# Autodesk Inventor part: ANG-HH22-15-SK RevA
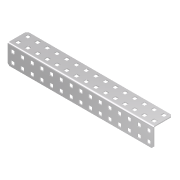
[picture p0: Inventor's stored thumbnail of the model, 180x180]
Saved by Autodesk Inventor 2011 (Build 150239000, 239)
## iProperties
Created: 2007-12
Part Number: ANG-HH22-15-SK RevA
Document SubType Name: Modeling
Density: 1 g/cm^3
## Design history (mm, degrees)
feature "Base1"
workplane "Work Plane1"
workplane "Work Plane2"
sketch "Sketch1" dims "d5" = 25.4
  geometry: L1 (2.286, -23.419)-(188.214, -23.419) reference; L2 (188.214, -23.419)-(190.5, -21.133) reference; L3 (190.5, -21.133)-(190.5, 0) reference; L4 (0, 0)-(190.5, 0) reference; L5 (0, 0)-(0, -21.133) reference; L6 (0, -21.133)-(2.286, -23.419) reference; L7 (186.461, -3.734)-(186.461, -7.341) reference; L8 (185.953, -7.849)-(182.347, -7.849) reference; L9 (181.839, -7.341)-(181.839, -3.734) reference; L10 (182.347, -3.226)-(185.953, -3.226) reference; L11 (173.761, -16.434)-(173.761, -20.041) reference; L12 (173.253, -20.549)-(169.647, -20.549) reference; L13 (169.139, -20.041)-(169.139, -16.434) reference; L14 (169.647, -15.926)-(173.253, -15.926) reference; L15 (173.761, -3.734)-(173.761, -7.341) reference; L16 (173.253, -7.849)-(169.647, -7.849) reference; L17 (169.139, -7.341)-(169.139, -3.734) reference; L18 (169.647, -3.226)-(173.253, -3.226) reference; L19 (161.061, -16.434)-(161.061, -20.041) reference; L20 (160.553, -20.549)-(156.947, -20.549) reference; L21 (156.439, -20.041)-(156.439, -16.434) reference; L22 (156.947, -15.926)-(160.553, -15.926) reference; L23 (161.061, -3.734)-(161.061, -7.341) reference; L24 (160.553, -7.849)-(156.947, -7.849) reference; L25 (156.439, -7.341)-(156.439, -3.734) reference; L26 (156.947, -3.226)-(160.553, -3.226) reference; L27 (148.361, -16.434)-(148.361, -20.041) reference; L28 (147.853, -20.549)-(144.247, -20.549) reference; L29 (143.739, -20.041)-(143.739, -16.434) reference; L30 (144.247, -15.926)-(147.853, -15.926) reference; L31 (148.361, -3.734)-(148.361, -7.341) reference; L32 (147.853, -7.849)-(144.247, -7.849) reference; L33 (143.739, -7.341)-(143.739, -3.734) reference; L34 (144.247, -3.226)-(147.853, -3.226) reference; L35 (135.661, -16.434)-(135.661, -20.041) reference; L36 (135.153, -20.549)-(131.547, -20.549) reference; L37 (131.039, -20.041)-(131.039, -16.434) reference; L38 (131.547, -15.926)-(135.153, -15.926) reference; L39 (135.661, -3.734)-(135.661, -7.341) reference; L40 (135.153, -7.849)-(131.547, -7.849) reference; L41 (131.039, -7.341)-(131.039, -3.734) reference; L42 (131.547, -3.226)-(135.153, -3.226) reference; L43 (122.961, -16.434)-(122.961, -20.041) reference; L44 (122.453, -20.549)-(118.847, -20.549) reference; L45 (118.339, -20.041)-(118.339, -16.434) reference; L46 (118.847, -15.926)-(122.453, -15.926) reference; L47 (122.961, -3.734)-(122.961, -7.341) reference; L48 (122.453, -7.849)-(118.847, -7.849) reference; L49 (118.339, -7.341)-(118.339, -3.734) reference; L50 (118.847, -3.226)-(122.453, -3.226) reference; L51 (110.261, -16.434)-(110.261, -20.041) reference; L52 (109.753, -20.549)-(106.147, -20.549) reference; L53 (105.639, -20.041)-(105.639, -16.434) reference; L54 (106.147, -15.926)-(109.753, -15.926) reference; L55 (110.261, -3.734)-(110.261, -7.341) reference; L56 (109.753, -7.849)-(106.147, -7.849) reference; L57 (105.639, -7.341)-(105.639, -3.734) reference; L58 (106.147, -3.226)-(109.753, -3.226) reference; L59 (97.561, -16.434)-(97.561, -20.041) reference; L60 (97.053, -20.549)-(93.447, -20.549) reference; L61 (92.939, -20.041)-(92.939, -16.434) reference; L62 (93.447, -15.926)-(97.053, -15.926) reference; L63 (97.561, -3.734)-(97.561, -7.341) reference; L64 (97.053, -7.849)-(93.447, -7.849) reference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; C1 r 2.311 at (184.15, -18.237); C2 r 2.311 at (171.45, -18.237); C3 r 2.311 at (158.75, -18.237); C4 r 2.311 at (146.05, -18.237); C5 r 2.311 at (133.35, -18.237); C6 r 2.311 at (120.65, -18.237); C7 r 2.311 at (107.95, -18.237); C8 r 2.311 at (95.25, -18.237); C9 r 2.311 at (82.55, -18.237); C10 r 2.311 at (69.85, -18.237); C11 r 2.311 at (57.15, -18.237); C12 r 2.311 at (44.45, -18.237); C13 r 2.311 at (31.75, -18.237); C14 r 2.311 at (19.05, -18.237); C15 r 2.311 at (6.35, -18.237); A1 r 0.508 centre (185.953, -7.341) between (185.953, -7.849) and (186.461, -7.341) reference; A2 r 0.508 centre (182.347, -7.341) between (181.839, -7.341) and (182.347, -7.849) reference; A3 r 0.508 centre (182.347, -3.734) between (182.347, -3.226) and (181.839, -3.734) reference; A4 r 0.508 centre (185.953, -3.734) between (186.461, -3.734) and (185.953, -3.226) reference; A5 r 0.508 centre (173.253, -20.041) between (173.253, -20.549) and (173.761, -20.041) reference; A6 r 0.508 centre (169.647, -20.041) between (169.139, -20.041) and (169.647, -20.549) reference; A7 r 0.508 centre (169.647, -16.434) between (169.647, -15.926) and (169.139, -16.434) reference; A8 r 0.508 centre (173.253, -16.434) between (173.761, -16.434) and (173.253, -15.926) reference; A9 r 0.508 centre (173.253, -7.341) between (173.253, -7.849) and (173.761, -7.341) reference; A10 r 0.508 centre (169.647, -7.341) between (169.139, -7.341) and (169.647, -7.849) reference; A11 r 0.508 centre (169.647, -3.734) between (169.647, -3.226) and (169.139, -3.734) reference; A12 r 0.508 centre (173.253, -3.734) between (173.761, -3.734) and (173.253, -3.226) reference; A13 r 0.508 centre (160.553, -20.041) between (160.553, -20.549) and (161.061, -20.041) reference; A14 r 0.508 centre (156.947, -20.041) between (156.439, -20.041) and (156.947, -20.549) reference; A15 r 0.508 centre (156.947, -16.434) between (156.947, -15.926) and (156.439, -16.434) reference; A16 r 0.508 centre (160.553, -16.434) between (161.061, -16.434) and (160.553, -15.926) reference; A17 r 0.508 centre (160.553, -7.341) between (160.553, -7.849) and (161.061, -7.341) reference; A18 r 0.508 centre (156.947, -7.341) between (156.439, -7.341) and (156.947, -7.849) reference; A19 r 0.508 centre (156.947, -3.734) between (156.947, -3.226) and (156.439, -3.734) reference; A20 r 0.508 centre (160.553, -3.734) between (161.061, -3.734) and (160.553, -3.226) reference; A21 r 0.508 centre (147.853, -20.041) between (147.853, -20.549) and (148.361, -20.041) reference; A22 r 0.508 centre (144.247, -20.041) between (143.739, -20.041) and (144.247, -20.549) reference; A23 r 0.508 centre (144.247, -16.434) between (144.247, -15.926) and (143.739, -16.434) reference; A24 r 0.508 centre (147.853, -16.434) between (148.361, -16.434) and (147.853, -15.926) reference; A25 r 0.508 centre (147.853, -7.341) between (147.853, -7.849) and (148.361, -7.341) reference; A26 r 0.508 centre (144.247, -7.341) between (143.739, -7.341) and (144.247, -7.849) reference; A27 r 0.508 centre (144.247, -3.734) between (144.247, -3.226) and (143.739, -3.734) reference; A28 r 0.508 centre (147.853, -3.734) between (148.361, -3.734) and (147.853, -3.226) reference; A29 r 0.508 centre (135.153, -20.041) between (135.153, -20.549) and (135.661, -20.041) reference; A30 r 0.508 centre (131.547, -20.041) between (131.039, -20.041) and (131.547, -20.549) reference; A31 r 0.508 centre (131.547, -16.434) between (131.547, -15.926) and (131.039, -16.434) reference; A32 r 0.508 centre (135.153, -16.434) between (135.661, -16.434) and (135.153, -15.926) reference; A33 r 0.508 centre (135.153, -7.341) between (135.153, -7.849) and (135.661, -7.341) reference; A34 r 0.508 centre (131.547, -7.341) between (131.039, -7.341) and (131.547, -7.849) reference; A35 r 0.508 centre (131.547, -3.734) between (131.547, -3.226) and (131.039, -3.734) reference; A36 r 0.508 centre (135.153, -3.734) between (135.661, -3.734) and (135.153, -3.226) reference; A37 r 0.508 centre (122.453, -20.041) between (122.453, -20.549) and (122.961, -20.041) reference; A38 r 0.508 centre (118.847, -20.041) between (118.339, -20.041) and (118.847, -20.549) reference; A39 r 0.508 centre (118.847, -16.434) between (118.847, -15.926) and (118.339, -16.434) reference; A40 r 0.508 centre (122.453, -16.434) between (122.961, -16.434) and (122.453, -15.926) reference; A41 r 0.508 centre (122.453, -7.341) between (122.453, -7.849) and (122.961, -7.341) reference; A42 r 0.508 centre (118.847, -7.341) between (118.339, -7.341) and (118.847, -7.849) reference; A43 r 0.508 centre (118.847, -3.734) between (118.847, -3.226) and (118.339, -3.734) reference; A44 r 0.508 centre (122.453, -3.734) between (122.961, -3.734) and (122.453, -3.226) reference; A45 r 0.508 centre (109.753, -20.041) between (109.753, -20.549) and (110.261, -20.041) reference; A46 r 0.508 centre (106.147, -20.041) between (105.639, -20.041) and (106.147, -20.549) reference; A47 r 0.508 centre (106.147, -16.434) between (106.147, -15.926) and (105.639, -16.434) reference; A48 r 0.508 centre (109.753, -16.434) between (110.261, -16.434) and (109.753, -15.926) reference; A49 r 0.508 centre (109.753, -7.341) between (109.753, -7.849) and (110.261, -7.341) reference; A50 r 0.508 centre (106.147, -7.341) between (105.639, -7.341) and (106.147, -7.849) reference; A51 r 0.508 centre (106.147, -3.734) between (106.147, -3.226) and (105.639, -3.734) reference; A52 r 0.508 centre (109.753, -3.734) between (110.261, -3.734) and (109.753, -3.226) reference; A53 r 0.508 centre (97.053, -20.041) between (97.053, -20.549) and (97.561, -20.041) reference; A54 r 0.508 centre (93.447, -20.041) between (92.939, -20.041) and (93.447, -20.549) reference; A55 r 0.508 centre (93.447, -16.434) between (93.447, -15.926) and (92.939, -16.434) reference; A56 r 0.508 centre (97.053, -16.434) between (97.561, -16.434) and (97.053, -15.926) reference; A57 r 0.508 centre (97.053, -7.341) between (97.053, -7.849) and (97.561, -7.341) reference; A58 r 0.508 centre (93.447, -7.341) between (92.939, -7.341) and (93.447, -7.849) reference; A59 r 0.508 centre (93.447, -3.734) between (93.447, -3.226) and (92.939, -3.734) reference; A60 r 0.508 centre (97.053, -3.734) between (97.561, -3.734) and (97.053, -3.226) reference; A61 r 0.508 centre (84.353, -20.041) between (84.353, -20.549) and (84.861, -20.041) reference; A62 r 0.508 centre (80.747, -20.041) between (80.239, -20.041) and (80.747, -20.549) reference; A63 r 0.508 centre (80.747, -16.434) between (80.747, -15.926) and (80.239, -16.434) reference; A64 r 0.508 centre (84.353, -16.434) between (84.861, -16.434) and (84.353, -15.926) reference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
  constraints: 15 centre point, 3 tangent, 1 horizontal, 28 other
  dimensions: "d2" = 12.7 distance of C1.centre C2.centre
sketch "Sketch2" dims "d12" = 25.4
  geometry: L1 (190.5, 21.133)-(190.5, 0) reference; L2 (190.5, 21.133)-(188.214, 23.419) reference; L3 (2.286, 23.419)-(188.214, 23.419) reference; L4 (2.286, 23.419)-(0, 21.133) reference; L5 (0, 0)-(0, 21.133) reference; L6 (190.5, 0)-(0, 0) reference; L7 (186.461, 7.341)-(186.461, 3.734) reference; L8 (185.953, 3.226)-(182.347, 3.226) reference; L9 (181.839, 3.734)-(181.839, 7.341) reference; L10 (182.347, 7.849)-(185.953, 7.849) reference; L11 (173.761, 20.041)-(173.761, 16.434) reference; L12 (173.253, 15.926)-(169.647, 15.926) reference; L13 (169.139, 16.434)-(169.139, 20.041) reference; L14 (169.647, 20.549)-(173.253, 20.549) reference; L15 (173.761, 7.341)-(173.761, 3.734) reference; L16 (173.253, 3.226)-(169.647, 3.226) reference; L17 (169.139, 3.734)-(169.139, 7.341) reference; L18 (169.647, 7.849)-(173.253, 7.849) reference; L19 (161.061, 20.041)-(161.061, 16.434) reference; L20 (160.553, 15.926)-(156.947, 15.926) reference; L21 (156.439, 16.434)-(156.439, 20.041) reference; L22 (156.947, 20.549)-(160.553, 20.549) reference; L23 (161.061, 7.341)-(161.061, 3.734) reference; L24 (160.553, 3.226)-(156.947, 3.226) reference; L25 (156.439, 3.734)-(156.439, 7.341) reference; L26 (156.947, 7.849)-(160.553, 7.849) reference; L27 (148.361, 20.041)-(148.361, 16.434) reference; L28 (147.853, 15.926)-(144.247, 15.926) reference; L29 (143.739, 16.434)-(143.739, 20.041) reference; L30 (144.247, 20.549)-(147.853, 20.549) reference; L31 (148.361, 7.341)-(148.361, 3.734) reference; L32 (147.853, 3.226)-(144.247, 3.226) reference; L33 (143.739, 3.734)-(143.739, 7.341) reference; L34 (144.247, 7.849)-(147.853, 7.849) reference; L35 (135.661, 20.041)-(135.661, 16.434) reference; L36 (135.153, 15.926)-(131.547, 15.926) reference; L37 (131.039, 16.434)-(131.039, 20.041) reference; L38 (131.547, 20.549)-(135.153, 20.549) reference; L39 (135.661, 7.341)-(135.661, 3.734) reference; L40 (135.153, 3.226)-(131.547, 3.226) reference; L41 (131.039, 3.734)-(131.039, 7.341) reference; L42 (131.547, 7.849)-(135.153, 7.849) reference; L43 (122.961, 20.041)-(122.961, 16.434) reference; L44 (122.453, 15.926)-(118.847, 15.926) reference; L45 (118.339, 16.434)-(118.339, 20.041) reference; L46 (118.847, 20.549)-(122.453, 20.549) reference; L47 (122.961, 7.341)-(122.961, 3.734) reference; L48 (122.453, 3.226)-(118.847, 3.226) reference; L49 (118.339, 3.734)-(118.339, 7.341) reference; L50 (118.847, 7.849)-(122.453, 7.849) reference; L51 (110.261, 20.041)-(110.261, 16.434) reference; L52 (109.753, 15.926)-(106.147, 15.926) reference; L53 (105.639, 16.434)-(105.639, 20.041) reference; L54 (106.147, 20.549)-(109.753, 20.549) reference; L55 (110.261, 7.341)-(110.261, 3.734) reference; L56 (109.753, 3.226)-(106.147, 3.226) reference; L57 (105.639, 3.734)-(105.639, 7.341) reference; L58 (106.147, 7.849)-(109.753, 7.849) reference; L59 (97.561, 20.041)-(97.561, 16.434) reference; L60 (97.053, 15.926)-(93.447, 15.926) reference; L61 (92.939, 16.434)-(92.939, 20.041) reference; L62 (93.447, 20.549)-(97.053, 20.549) reference; L63 (97.561, 7.341)-(97.561, 3.734) reference; L64 (97.053, 3.226)-(93.447, 3.226) reference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; C1 r 2.311 at (184.15, 18.237); C2 r 2.311 at (171.45, 18.237); C3 r 2.311 at (158.75, 18.237); C4 r 2.311 at (146.05, 18.237); C5 r 2.311 at (133.35, 18.237); C6 r 2.311 at (120.65, 18.237); C7 r 2.311 at (107.95, 18.237); C8 r 2.311 at (95.25, 18.237); C9 r 2.311 at (82.55, 18.237); C10 r 2.311 at (69.85, 18.237); C11 r 2.311 at (57.15, 18.237); C12 r 2.311 at (44.45, 18.237); C13 r 2.311 at (31.75, 18.237); C14 r 2.311 at (19.05, 18.237); C15 r 2.311 at (6.35, 18.237); A1 r 0.508 centre (185.953, 3.734) between (185.953, 3.226) and (186.461, 3.734) reference; A2 r 0.508 centre (182.347, 3.734) between (181.839, 3.734) and (182.347, 3.226) reference; A3 r 0.508 centre (182.347, 7.341) between (182.347, 7.849) and (181.839, 7.341) reference; A4 r 0.508 centre (185.953, 7.341) between (186.461, 7.341) and (185.953, 7.849) reference; A5 r 0.508 centre (173.253, 16.434) between (173.253, 15.926) and (173.761, 16.434) reference; A6 r 0.508 centre (169.647, 16.434) between (169.139, 16.434) and (169.647, 15.926) reference; A7 r 0.508 centre (169.647, 20.041) between (169.647, 20.549) and (169.139, 20.041) reference; A8 r 0.508 centre (173.253, 20.041) between (173.761, 20.041) and (173.253, 20.549) reference; A9 r 0.508 centre (173.253, 3.734) between (173.253, 3.226) and (173.761, 3.734) reference; A10 r 0.508 centre (169.647, 3.734) between (169.139, 3.734) and (169.647, 3.226) reference; A11 r 0.508 centre (169.647, 7.341) between (169.647, 7.849) and (169.139, 7.341) reference; A12 r 0.508 centre (173.253, 7.341) between (173.761, 7.341) and (173.253, 7.849) reference; A13 r 0.508 centre (160.553, 16.434) between (160.553, 15.926) and (161.061, 16.434) reference; A14 r 0.508 centre (156.947, 16.434) between (156.439, 16.434) and (156.947, 15.926) reference; A15 r 0.508 centre (156.947, 20.041) between (156.947, 20.549) and (156.439, 20.041) reference; A16 r 0.508 centre (160.553, 20.041) between (161.061, 20.041) and (160.553, 20.549) reference; A17 r 0.508 centre (160.553, 3.734) between (160.553, 3.226) and (161.061, 3.734) reference; A18 r 0.508 centre (156.947, 3.734) between (156.439, 3.734) and (156.947, 3.226) reference; A19 r 0.508 centre (156.947, 7.341) between (156.947, 7.849) and (156.439, 7.341) reference; A20 r 0.508 centre (160.553, 7.341) between (161.061, 7.341) and (160.553, 7.849) reference; A21 r 0.508 centre (147.853, 16.434) between (147.853, 15.926) and (148.361, 16.434) reference; A22 r 0.508 centre (144.247, 16.434) between (143.739, 16.434) and (144.247, 15.926) reference; A23 r 0.508 centre (144.247, 20.041) between (144.247, 20.549) and (143.739, 20.041) reference; A24 r 0.508 centre (147.853, 20.041) between (148.361, 20.041) and (147.853, 20.549) reference; A25 r 0.508 centre (147.853, 3.734) between (147.853, 3.226) and (148.361, 3.734) reference; A26 r 0.508 centre (144.247, 3.734) between (143.739, 3.734) and (144.247, 3.226) reference; A27 r 0.508 centre (144.247, 7.341) between (144.247, 7.849) and (143.739, 7.341) reference; A28 r 0.508 centre (147.853, 7.341) between (148.361, 7.341) and (147.853, 7.849) reference; A29 r 0.508 centre (135.153, 16.434) between (135.153, 15.926) and (135.661, 16.434) reference; A30 r 0.508 centre (131.547, 16.434) between (131.039, 16.434) and (131.547, 15.926) reference; A31 r 0.508 centre (131.547, 20.041) between (131.547, 20.549) and (131.039, 20.041) reference; A32 r 0.508 centre (135.153, 20.041) between (135.661, 20.041) and (135.153, 20.549) reference; A33 r 0.508 centre (135.153, 3.734) between (135.153, 3.226) and (135.661, 3.734) reference; A34 r 0.508 centre (131.547, 3.734) between (131.039, 3.734) and (131.547, 3.226) reference; A35 r 0.508 centre (131.547, 7.341) between (131.547, 7.849) and (131.039, 7.341) reference; A36 r 0.508 centre (135.153, 7.341) between (135.661, 7.341) and (135.153, 7.849) reference; A37 r 0.508 centre (122.453, 16.434) between (122.453, 15.926) and (122.961, 16.434) reference; A38 r 0.508 centre (118.847, 16.434) between (118.339, 16.434) and (118.847, 15.926) reference; A39 r 0.508 centre (118.847, 20.041) between (118.847, 20.549) and (118.339, 20.041) reference; A40 r 0.508 centre (122.453, 20.041) between (122.961, 20.041) and (122.453, 20.549) reference; A41 r 0.508 centre (122.453, 3.734) between (122.453, 3.226) and (122.961, 3.734) reference; A42 r 0.508 centre (118.847, 3.734) between (118.339, 3.734) and (118.847, 3.226) reference; A43 r 0.508 centre (118.847, 7.341) between (118.847, 7.849) and (118.339, 7.341) reference; A44 r 0.508 centre (122.453, 7.341) between (122.961, 7.341) and (122.453, 7.849) reference; A45 r 0.508 centre (109.753, 16.434) between (109.753, 15.926) and (110.261, 16.434) reference; A46 r 0.508 centre (106.147, 16.434) between (105.639, 16.434) and (106.147, 15.926) reference; A47 r 0.508 centre (106.147, 20.041) between (106.147, 20.549) and (105.639, 20.041) reference; A48 r 0.508 centre (109.753, 20.041) between (110.261, 20.041) and (109.753, 20.549) reference; A49 r 0.508 centre (109.753, 3.734) between (109.753, 3.226) and (110.261, 3.734) reference; A50 r 0.508 centre (106.147, 3.734) between (105.639, 3.734) and (106.147, 3.226) reference; A51 r 0.508 centre (106.147, 7.341) between (106.147, 7.849) and (105.639, 7.341) reference; A52 r 0.508 centre (109.753, 7.341) between (110.261, 7.341) and (109.753, 7.849) reference; A53 r 0.508 centre (97.053, 16.434) between (97.053, 15.926) and (97.561, 16.434) reference; A54 r 0.508 centre (93.447, 16.434) between (92.939, 16.434) and (93.447, 15.926) reference; A55 r 0.508 centre (93.447, 20.041) between (93.447, 20.549) and (92.939, 20.041) reference; A56 r 0.508 centre (97.053, 20.041) between (97.561, 20.041) and (97.053, 20.549) reference; A57 r 0.508 centre (97.053, 3.734) between (97.053, 3.226) and (97.561, 3.734) reference; A58 r 0.508 centre (93.447, 3.734) between (92.939, 3.734) and (93.447, 3.226) reference; A59 r 0.508 centre (93.447, 7.341) between (93.447, 7.849) and (92.939, 7.341) reference; A60 r 0.508 centre (97.053, 7.341) between (97.561, 7.341) and (97.053, 7.849) reference; A61 r 0.508 centre (84.353, 16.434) between (84.353, 15.926) and (84.861, 16.434) reference; A62 r 0.508 centre (80.747, 16.434) between (80.239, 16.434) and (80.747, 15.926) reference; A63 r 0.508 centre (80.747, 20.041) between (80.747, 20.549) and (80.239, 20.041) reference; A64 r 0.508 centre (84.353, 20.041) between (84.861, 20.041) and (84.353, 20.549) reference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
  constraints: 15 centre point, 4 tangent, 1 horizontal, 28 other
  dimensions: "d9" = 12.7 distance of C1.centre C2.centre
sketch "Sketch3"
  geometry: L1 (2.286, -23.419)-(188.214, -23.419) reference; L2 (188.214, -23.419)-(190.5, -21.133) reference; L3 (190.5, -21.133)-(190.5, 0) reference; L4 (190.5, 0)-(0, 0) reference; L5 (0, 0)-(0, -21.133) reference; L6 (0, -21.133)-(2.286, -23.419) reference; L7 (181.839, -3.734)-(181.839, -7.341) reference; L8 (185.953, -3.226)-(182.347, -3.226) reference; L9 (186.461, -7.341)-(186.461, -3.734) reference; L10 (182.347, -7.849)-(185.953, -7.849) reference; L11 (169.139, -16.434)-(169.139, -20.041) reference; L12 (173.253, -15.926)-(169.647, -15.926) reference; L13 (173.761, -20.041)-(173.761, -16.434) reference; L14 (169.647, -20.549)-(173.253, -20.549) reference; L15 (169.139, -3.734)-(169.139, -7.341) reference; L16 (173.253, -3.226)-(169.647, -3.226) reference; L17 (173.761, -7.341)-(173.761, -3.734) reference; L18 (169.647, -7.849)-(173.253, -7.849) reference; L19 (156.439, -16.434)-(156.439, -20.041) reference; L20 (160.553, -15.926)-(156.947, -15.926) reference; L21 (161.061, -20.041)-(161.061, -16.434) reference; L22 (156.947, -20.549)-(160.553, -20.549) reference; L23 (156.439, -3.734)-(156.439, -7.341) reference; L24 (160.553, -3.226)-(156.947, -3.226) reference; L25 (161.061, -7.341)-(161.061, -3.734) reference; L26 (156.947, -7.849)-(160.553, -7.849) reference; L27 (143.739, -16.434)-(143.739, -20.041) reference; L28 (147.853, -15.926)-(144.247, -15.926) reference; L29 (148.361, -20.041)-(148.361, -16.434) reference; L30 (144.247, -20.549)-(147.853, -20.549) reference; L31 (143.739, -3.734)-(143.739, -7.341) reference; L32 (147.853, -3.226)-(144.247, -3.226) reference; L33 (148.361, -7.341)-(148.361, -3.734) reference; L34 (144.247, -7.849)-(147.853, -7.849) reference; L35 (131.039, -16.434)-(131.039, -20.041) reference; L36 (135.153, -15.926)-(131.547, -15.926) reference; L37 (135.661, -20.041)-(135.661, -16.434) reference; L38 (131.547, -20.549)-(135.153, -20.549) reference; L39 (131.039, -3.734)-(131.039, -7.341) reference; L40 (135.153, -3.226)-(131.547, -3.226) reference; L41 (135.661, -7.341)-(135.661, -3.734) reference; L42 (131.547, -7.849)-(135.153, -7.849) reference; L43 (118.339, -16.434)-(118.339, -20.041) reference; L44 (122.453, -15.926)-(118.847, -15.926) reference; L45 (122.961, -20.041)-(122.961, -16.434) reference; L46 (118.847, -20.549)-(122.453, -20.549) reference; L47 (118.339, -3.734)-(118.339, -7.341) reference; L48 (122.453, -3.226)-(118.847, -3.226) reference; L49 (122.961, -7.341)-(122.961, -3.734) reference; L50 (118.847, -7.849)-(122.453, -7.849) reference; L51 (105.639, -16.434)-(105.639, -20.041) reference; L52 (109.753, -15.926)-(106.147, -15.926) reference; L53 (110.261, -20.041)-(110.261, -16.434) reference; L54 (106.147, -20.549)-(109.753, -20.549) reference; L55 (105.639, -3.734)-(105.639, -7.341) reference; L56 (109.753, -3.226)-(106.147, -3.226) reference; L57 (110.261, -7.341)-(110.261, -3.734) reference; L58 (106.147, -7.849)-(109.753, -7.849) reference; L59 (92.939, -16.434)-(92.939, -20.041) reference; L60 (97.053, -15.926)-(93.447, -15.926) reference; L61 (97.561, -20.041)-(97.561, -16.434) reference; L62 (93.447, -20.549)-(97.053, -20.549) reference; L63 (92.939, -3.734)-(92.939, -7.341) reference; L64 (97.053, -3.226)-(93.447, -3.226) reference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; C1 r 2.311 at (6.35, -18.237); C2 r 2.311 at (6.35, -5.537); C3 r 2.311 at (184.15, -18.237); C4 r 2.311 at (184.15, -5.537); A1 r 0.508 centre (182.347, -3.734) between (182.347, -3.226) and (181.839, -3.734) reference; A2 r 0.508 centre (185.953, -3.734) between (186.461, -3.734) and (185.953, -3.226) reference; A3 r 0.508 centre (185.953, -7.341) between (185.953, -7.849) and (186.461, -7.341) reference; A4 r 0.508 centre (182.347, -7.341) between (181.839, -7.341) and (182.347, -7.849) reference; A5 r 0.508 centre (169.647, -16.434) between (169.647, -15.926) and (169.139, -16.434) reference; A6 r 0.508 centre (173.253, -16.434) between (173.761, -16.434) and (173.253, -15.926) reference; A7 r 0.508 centre (173.253, -20.041) between (173.253, -20.549) and (173.761, -20.041) reference; A8 r 0.508 centre (169.647, -20.041) between (169.139, -20.041) and (169.647, -20.549) reference; A9 r 0.508 centre (169.647, -3.734) between (169.647, -3.226) and (169.139, -3.734) reference; A10 r 0.508 centre (173.253, -3.734) between (173.761, -3.734) and (173.253, -3.226) reference; A11 r 0.508 centre (173.253, -7.341) between (173.253, -7.849) and (173.761, -7.341) reference; A12 r 0.508 centre (169.647, -7.341) between (169.139, -7.341) and (169.647, -7.849) reference; A13 r 0.508 centre (156.947, -16.434) between (156.947, -15.926) and (156.439, -16.434) reference; A14 r 0.508 centre (160.553, -16.434) between (161.061, -16.434) and (160.553, -15.926) reference; A15 r 0.508 centre (160.553, -20.041) between (160.553, -20.549) and (161.061, -20.041) reference; A16 r 0.508 centre (156.947, -20.041) between (156.439, -20.041) and (156.947, -20.549) reference; A17 r 0.508 centre (156.947, -3.734) between (156.947, -3.226) and (156.439, -3.734) reference; A18 r 0.508 centre (160.553, -3.734) between (161.061, -3.734) and (160.553, -3.226) reference; A19 r 0.508 centre (160.553, -7.341) between (160.553, -7.849) and (161.061, -7.341) reference; A20 r 0.508 centre (156.947, -7.341) between (156.439, -7.341) and (156.947, -7.849) reference; A21 r 0.508 centre (144.247, -16.434) between (144.247, -15.926) and (143.739, -16.434) reference; A22 r 0.508 centre (147.853, -16.434) between (148.361, -16.434) and (147.853, -15.926) reference; A23 r 0.508 centre (147.853, -20.041) between (147.853, -20.549) and (148.361, -20.041) reference; A24 r 0.508 centre (144.247, -20.041) between (143.739, -20.041) and (144.247, -20.549) reference; A25 r 0.508 centre (144.247, -3.734) between (144.247, -3.226) and (143.739, -3.734) reference; A26 r 0.508 centre (147.853, -3.734) between (148.361, -3.734) and (147.853, -3.226) reference; A27 r 0.508 centre (147.853, -7.341) between (147.853, -7.849) and (148.361, -7.341) reference; A28 r 0.508 centre (144.247, -7.341) between (143.739, -7.341) and (144.247, -7.849) reference; A29 r 0.508 centre (131.547, -16.434) between (131.547, -15.926) and (131.039, -16.434) reference; A30 r 0.508 centre (135.153, -16.434) between (135.661, -16.434) and (135.153, -15.926) reference; A31 r 0.508 centre (135.153, -20.041) between (135.153, -20.549) and (135.661, -20.041) reference; A32 r 0.508 centre (131.547, -20.041) between (131.039, -20.041) and (131.547, -20.549) reference; A33 r 0.508 centre (131.547, -3.734) between (131.547, -3.226) and (131.039, -3.734) reference; A34 r 0.508 centre (135.153, -3.734) between (135.661, -3.734) and (135.153, -3.226) reference; A35 r 0.508 centre (135.153, -7.341) between (135.153, -7.849) and (135.661, -7.341) reference; A36 r 0.508 centre (131.547, -7.341) between (131.039, -7.341) and (131.547, -7.849) reference; A37 r 0.508 centre (118.847, -16.434) between (118.847, -15.926) and (118.339, -16.434) reference; A38 r 0.508 centre (122.453, -16.434) between (122.961, -16.434) and (122.453, -15.926) reference; A39 r 0.508 centre (122.453, -20.041) between (122.453, -20.549) and (122.961, -20.041) reference; A40 r 0.508 centre (118.847, -20.041) between (118.339, -20.041) and (118.847, -20.549) reference; A41 r 0.508 centre (118.847, -3.734) between (118.847, -3.226) and (118.339, -3.734) reference; A42 r 0.508 centre (122.453, -3.734) between (122.961, -3.734) and (122.453, -3.226) reference; A43 r 0.508 centre (122.453, -7.341) between (122.453, -7.849) and (122.961, -7.341) reference; A44 r 0.508 centre (118.847, -7.341) between (118.339, -7.341) and (118.847, -7.849) reference; A45 r 0.508 centre (106.147, -16.434) between (106.147, -15.926) and (105.639, -16.434) reference; A46 r 0.508 centre (109.753, -16.434) between (110.261, -16.434) and (109.753, -15.926) reference; A47 r 0.508 centre (109.753, -20.041) between (109.753, -20.549) and (110.261, -20.041) reference; A48 r 0.508 centre (106.147, -20.041) between (105.639, -20.041) and (106.147, -20.549) reference; A49 r 0.508 centre (106.147, -3.734) between (106.147, -3.226) and (105.639, -3.734) reference; A50 r 0.508 centre (109.753, -3.734) between (110.261, -3.734) and (109.753, -3.226) reference; A51 r 0.508 centre (109.753, -7.341) between (109.753, -7.849) and (110.261, -7.341) reference; A52 r 0.508 centre (106.147, -7.341) between (105.639, -7.341) and (106.147, -7.849) reference; A53 r 0.508 centre (93.447, -16.434) between (93.447, -15.926) and (92.939, -16.434) reference; A54 r 0.508 centre (97.053, -16.434) between (97.561, -16.434) and (97.053, -15.926) reference; A55 r 0.508 centre (97.053, -20.041) between (97.053, -20.549) and (97.561, -20.041) reference; A56 r 0.508 centre (93.447, -20.041) between (92.939, -20.041) and (93.447, -20.549) reference; A57 r 0.508 centre (93.447, -3.734) between (93.447, -3.226) and (92.939, -3.734) reference; A58 r 0.508 centre (97.053, -3.734) between (97.561, -3.734) and (97.053, -3.226) reference; A59 r 0.508 centre (97.053, -7.341) between (97.053, -7.849) and (97.561, -7.341) reference; A60 r 0.508 centre (93.447, -7.341) between (92.939, -7.341) and (93.447, -7.849) reference; A61 r 0.508 centre (80.747, -16.434) between (80.747, -15.926) and (80.239, -16.434) reference; A62 r 0.508 centre (84.353, -16.434) between (84.861, -16.434) and (84.353, -15.926) reference; A63 r 0.508 centre (84.353, -20.041) between (84.353, -20.549) and (84.861, -20.041) reference; A64 r 0.508 centre (80.747, -20.041) between (80.239, -20.041) and (80.747, -20.549) reference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
  constraints: 15 tangent, 4 centre point
sketch "Sketch4"
  geometry: L1 (0, -21.133)-(0, 0) reference; L2 (0, -21.133)-(2.286, -23.419) reference; L3 (188.214, -23.419)-(2.286, -23.419) reference; L4 (188.214, -23.419)-(190.5, -21.133) reference; L5 (190.5, 0)-(190.5, -21.133) reference; L6 (190.5, 0)-(0, 0) reference; L7 (8.661, -7.341)-(8.661, -3.734) reference; L8 (4.547, -7.849)-(8.153, -7.849) reference; L9 (4.039, -3.734)-(4.039, -7.341) reference; L10 (8.153, -3.226)-(4.547, -3.226) reference; L11 (21.361, -20.041)-(21.361, -16.434) reference; L12 (17.247, -20.549)-(20.853, -20.549) reference; L13 (16.739, -16.434)-(16.739, -20.041) reference; L14 (20.853, -15.926)-(17.247, -15.926) reference; L15 (21.361, -7.341)-(21.361, -3.734) reference; L16 (17.247, -7.849)-(20.853, -7.849) reference; L17 (16.739, -3.734)-(16.739, -7.341) reference; L18 (20.853, -3.226)-(17.247, -3.226) reference; L19 (34.061, -20.041)-(34.061, -16.434) reference; L20 (29.947, -20.549)-(33.553, -20.549) reference; L21 (29.439, -16.434)-(29.439, -20.041) reference; L22 (33.553, -15.926)-(29.947, -15.926) reference; L23 (34.061, -7.341)-(34.061, -3.734) reference; L24 (29.947, -7.849)-(33.553, -7.849) reference; L25 (29.439, -3.734)-(29.439, -7.341) reference; L26 (33.553, -3.226)-(29.947, -3.226) reference; L27 (46.761, -20.041)-(46.761, -16.434) reference; L28 (42.647, -20.549)-(46.253, -20.549) reference; L29 (42.139, -16.434)-(42.139, -20.041) reference; L30 (46.253, -15.926)-(42.647, -15.926) reference; L31 (46.761, -7.341)-(46.761, -3.734) reference; L32 (42.647, -7.849)-(46.253, -7.849) reference; L33 (42.139, -3.734)-(42.139, -7.341) reference; L34 (46.253, -3.226)-(42.647, -3.226) reference; L35 (59.461, -20.041)-(59.461, -16.434) reference; L36 (55.347, -20.549)-(58.953, -20.549) reference; L37 (54.839, -16.434)-(54.839, -20.041) reference; L38 (58.953, -15.926)-(55.347, -15.926) reference; L39 (59.461, -7.341)-(59.461, -3.734) reference; L40 (55.347, -7.849)-(58.953, -7.849) reference; L41 (54.839, -3.734)-(54.839, -7.341) reference; L42 (58.953, -3.226)-(55.347, -3.226) reference; L43 (72.161, -20.041)-(72.161, -16.434) reference; L44 (68.047, -20.549)-(71.653, -20.549) reference; L45 (67.539, -16.434)-(67.539, -20.041) reference; L46 (71.653, -15.926)-(68.047, -15.926) reference; L47 (72.161, -7.341)-(72.161, -3.734) reference; L48 (68.047, -7.849)-(71.653, -7.849) reference; L49 (67.539, -3.734)-(67.539, -7.341) reference; L50 (71.653, -3.226)-(68.047, -3.226) reference; L51 (84.861, -20.041)-(84.861, -16.434) reference; L52 (80.747, -20.549)-(84.353, -20.549) reference; L53 (80.239, -16.434)-(80.239, -20.041) reference; L54 (84.353, -15.926)-(80.747, -15.926) reference; L55 (84.861, -7.341)-(84.861, -3.734) reference; L56 (80.747, -7.849)-(84.353, -7.849) reference; L57 (80.239, -3.734)-(80.239, -7.341) reference; L58 (84.353, -3.226)-(80.747, -3.226) reference; L59 (97.561, -20.041)-(97.561, -16.434) reference; L60 (93.447, -20.549)-(97.053, -20.549) reference; L61 (92.939, -16.434)-(92.939, -20.041) reference; L62 (97.053, -15.926)-(93.447, -15.926) reference; L63 (97.561, -7.341)-(97.561, -3.734) reference; L64 (93.447, -7.849)-(97.053, -7.849) reference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; C1 r 2.311 at (184.15, -5.537); C2 r 2.311 at (184.15, -18.237); C3 r 2.311 at (6.35, -5.537); C4 r 2.311 at (6.35, -18.237); A1 r 0.508 centre (8.153, -7.341) between (8.153, -7.849) and (8.661, -7.341) reference; A2 r 0.508 centre (4.547, -7.341) between (4.039, -7.341) and (4.547, -7.849) reference; A3 r 0.508 centre (4.547, -3.734) between (4.547, -3.226) and (4.039, -3.734) reference; A4 r 0.508 centre (8.153, -3.734) between (8.661, -3.734) and (8.153, -3.226) reference; A5 r 0.508 centre (20.853, -20.041) between (20.853, -20.549) and (21.361, -20.041) reference; A6 r 0.508 centre (17.247, -20.041) between (16.739, -20.041) and (17.247, -20.549) reference; A7 r 0.508 centre (17.247, -16.434) between (17.247, -15.926) and (16.739, -16.434) reference; A8 r 0.508 centre (20.853, -16.434) between (21.361, -16.434) and (20.853, -15.926) reference; A9 r 0.508 centre (20.853, -7.341) between (20.853, -7.849) and (21.361, -7.341) reference; A10 r 0.508 centre (17.247, -7.341) between (16.739, -7.341) and (17.247, -7.849) reference; A11 r 0.508 centre (17.247, -3.734) between (17.247, -3.226) and (16.739, -3.734) reference; A12 r 0.508 centre (20.853, -3.734) between (21.361, -3.734) and (20.853, -3.226) reference; A13 r 0.508 centre (33.553, -20.041) between (33.553, -20.549) and (34.061, -20.041) reference; A14 r 0.508 centre (29.947, -20.041) between (29.439, -20.041) and (29.947, -20.549) reference; A15 r 0.508 centre (29.947, -16.434) between (29.947, -15.926) and (29.439, -16.434) reference; A16 r 0.508 centre (33.553, -16.434) between (34.061, -16.434) and (33.553, -15.926) reference; A17 r 0.508 centre (33.553, -7.341) between (33.553, -7.849) and (34.061, -7.341) reference; A18 r 0.508 centre (29.947, -7.341) between (29.439, -7.341) and (29.947, -7.849) reference; A19 r 0.508 centre (29.947, -3.734) between (29.947, -3.226) and (29.439, -3.734) reference; A20 r 0.508 centre (33.553, -3.734) between (34.061, -3.734) and (33.553, -3.226) reference; A21 r 0.508 centre (46.253, -20.041) between (46.253, -20.549) and (46.761, -20.041) reference; A22 r 0.508 centre (42.647, -20.041) between (42.139, -20.041) and (42.647, -20.549) reference; A23 r 0.508 centre (42.647, -16.434) between (42.647, -15.926) and (42.139, -16.434) reference; A24 r 0.508 centre (46.253, -16.434) between (46.761, -16.434) and (46.253, -15.926) reference; A25 r 0.508 centre (46.253, -7.341) between (46.253, -7.849) and (46.761, -7.341) reference; A26 r 0.508 centre (42.647, -7.341) between (42.139, -7.341) and (42.647, -7.849) reference; A27 r 0.508 centre (42.647, -3.734) between (42.647, -3.226) and (42.139, -3.734) reference; A28 r 0.508 centre (46.253, -3.734) between (46.761, -3.734) and (46.253, -3.226) reference; A29 r 0.508 centre (58.953, -20.041) between (58.953, -20.549) and (59.461, -20.041) reference; A30 r 0.508 centre (55.347, -20.041) between (54.839, -20.041) and (55.347, -20.549) reference; A31 r 0.508 centre (55.347, -16.434) between (55.347, -15.926) and (54.839, -16.434) reference; A32 r 0.508 centre (58.953, -16.434) between (59.461, -16.434) and (58.953, -15.926) reference; A33 r 0.508 centre (58.953, -7.341) between (58.953, -7.849) and (59.461, -7.341) reference; A34 r 0.508 centre (55.347, -7.341) between (54.839, -7.341) and (55.347, -7.849) reference; A35 r 0.508 centre (55.347, -3.734) between (55.347, -3.226) and (54.839, -3.734) reference; A36 r 0.508 centre (58.953, -3.734) between (59.461, -3.734) and (58.953, -3.226) reference; A37 r 0.508 centre (71.653, -20.041) between (71.653, -20.549) and (72.161, -20.041) reference; A38 r 0.508 centre (68.047, -20.041) between (67.539, -20.041) and (68.047, -20.549) reference; A39 r 0.508 centre (68.047, -16.434) between (68.047, -15.926) and (67.539, -16.434) reference; A40 r 0.508 centre (71.653, -16.434) between (72.161, -16.434) and (71.653, -15.926) reference; A41 r 0.508 centre (71.653, -7.341) between (71.653, -7.849) and (72.161, -7.341) reference; A42 r 0.508 centre (68.047, -7.341) between (67.539, -7.341) and (68.047, -7.849) reference; A43 r 0.508 centre (68.047, -3.734) between (68.047, -3.226) and (67.539, -3.734) reference; A44 r 0.508 centre (71.653, -3.734) between (72.161, -3.734) and (71.653, -3.226) reference; A45 r 0.508 centre (84.353, -20.041) between (84.353, -20.549) and (84.861, -20.041) reference; A46 r 0.508 centre (80.747, -20.041) between (80.239, -20.041) and (80.747, -20.549) reference; A47 r 0.508 centre (80.747, -16.434) between (80.747, -15.926) and (80.239, -16.434) reference; A48 r 0.508 centre (84.353, -16.434) between (84.861, -16.434) and (84.353, -15.926) reference; A49 r 0.508 centre (84.353, -7.341) between (84.353, -7.849) and (84.861, -7.341) reference; A50 r 0.508 centre (80.747, -7.341) between (80.239, -7.341) and (80.747, -7.849) reference; A51 r 0.508 centre (80.747, -3.734) between (80.747, -3.226) and (80.239, -3.734) reference; A52 r 0.508 centre (84.353, -3.734) between (84.861, -3.734) and (84.353, -3.226) reference; A53 r 0.508 centre (97.053, -20.041) between (97.053, -20.549) and (97.561, -20.041) reference; A54 r 0.508 centre (93.447, -20.041) between (92.939, -20.041) and (93.447, -20.549) reference; A55 r 0.508 centre (93.447, -16.434) between (93.447, -15.926) and (92.939, -16.434) reference; A56 r 0.508 centre (97.053, -16.434) between (97.561, -16.434) and (97.053, -15.926) reference; A57 r 0.508 centre (97.053, -7.341) between (97.053, -7.849) and (97.561, -7.341) reference; A58 r 0.508 centre (93.447, -7.341) between (92.939, -7.341) and (93.447, -7.849) reference; A59 r 0.508 centre (93.447, -3.734) between (93.447, -3.226) and (92.939, -3.734) reference; A60 r 0.508 centre (97.053, -3.734) between (97.561, -3.734) and (97.053, -3.226) reference; A61 r 0.508 centre (109.753, -20.041) between (109.753, -20.549) and (110.261, -20.041) reference; A62 r 0.508 centre (106.147, -20.041) between (105.639, -20.041) and (106.147, -20.549) reference; A63 r 0.508 centre (106.147, -16.434) between (106.147, -15.926) and (105.639, -16.434) reference; A64 r 0.508 centre (109.753, -16.434) between (110.261, -16.434) and (109.753, -15.926) reference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
  constraints: 16 tangent, 4 centre point
body "Solid1"
